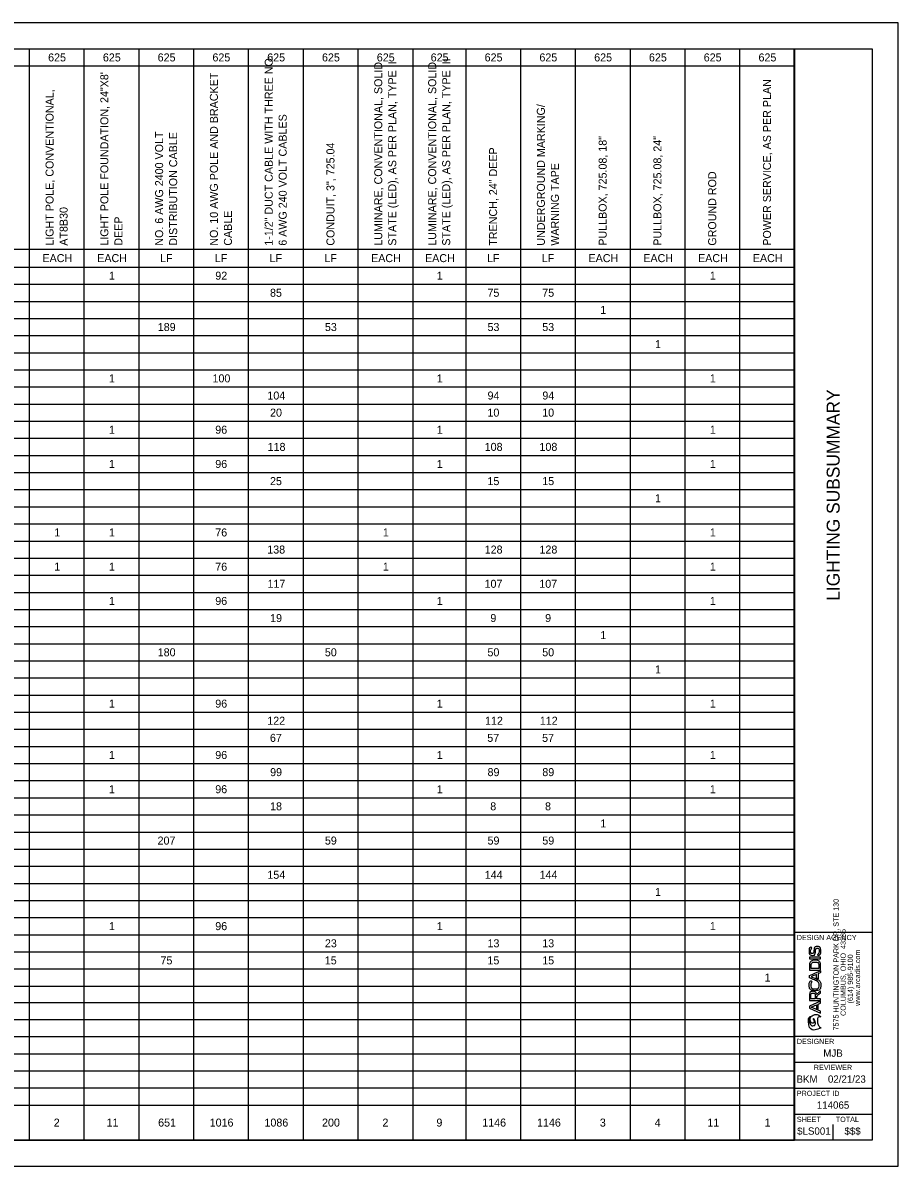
# Model space of a CAD drawing. Extents: x 0 to 34, y 0 to 22.
# Drawn here: x 17.16 to 34, y 0 to 22 of the extents above; entities that cross this region are included whole.
import ezdxf

# ---------------------------------------------------------------- set-up
doc = ezdxf.new("R2010")
doc.units = 0
for name, color, linetype in [('SH_Border', 7, 'Continuous'), ('SH_Cut_Line', 7, 'Continuous'), ('SH_Data', 7, 'Continuous'), ('SH_Text', 7, 'Continuous')]:
    doc.layers.add(name, color=color, linetype=linetype)

msp = doc.modelspace()

# ---------------------------------------------------------------- linework, layer by layer
at = {"layer": 'SH_Border'}
for p, q in [((32, 0.5), (32, 21.5)), ((32, 4.5), (33.5, 4.5)), ((32, 2.5), (33.5, 2.5)), ((32, 2), (33.5, 2)), ((32, 1.5), (33.5, 1.5)), ((32, 1), (33.5, 1))]:
    msp.add_line(p, q, dxfattribs=at)
msp.add_lwpolyline([(1.5, 21.5), (33.5, 21.5), (33.5, 0.5), (1.5, 0.5)], close=True, dxfattribs=at)
at = {"layer": 'SH_Cut_Line'}
msp.add_lwpolyline([(0, 0), (34, 0), (34, 22), (0, 22)], close=True, dxfattribs=at)
at = {"layer": 'SH_Data'}
for p, q in [((32.507, 4.022), (32.292, 4.022)), ((32.292, 4.022), (32.292, 3.988)), ((32.507, 4.022), (32.292, 4.022)), ((32.292, 4.022), (32.292, 3.988)), ((32.292, 3.988), (32.507, 3.988)), ((32.292, 3.988), (32.507, 3.988)), ((32.507, 3.988), (32.507, 4.022)), ((32.507, 3.988), (32.507, 4.022)), ((32.75, 3.5), (32.75, 3.5)), ((32.75, 3.5), (32.75, 3.5)), ((32.75, 3.5), (32.75, 3.5)), ((32.507, 3.175), (32.292, 3.079)), ((32.507, 3.175), (32.292, 3.079)), ((32.328, 3.06), (32.431, 3.105)), ((32.328, 3.06), (32.431, 3.105)), ((32.431, 3.105), (32.431, 3.034)), ((32.431, 3.105), (32.431, 3.034)), ((32.462, 3.119), (32.507, 3.139)), ((32.462, 3.119), (32.507, 3.139)), ((32.462, 3.02), (32.462, 3.119)), ((32.462, 3.02), (32.462, 3.119)), ((32.507, 3.139), (32.507, 3.175)), ((32.507, 3.139), (32.507, 3.175)), ((32.292, 3.079), (32.292, 3.041)), ((32.292, 3.079), (32.292, 3.041)), ((32.292, 3.041), (32.507, 2.945)), ((32.292, 3.041), (32.507, 2.945)), ((32.507, 2.981), (32.328, 3.06)), ((32.507, 2.981), (32.328, 3.06)), ((32.431, 3.034), (32.462, 3.02)), ((32.431, 3.034), (32.462, 3.02)), ((32.507, 2.945), (32.507, 2.981)), ((32.507, 2.945), (32.507, 2.981)), ((32.375, 0.675), (32.375, 0.675)), ((32.75, 0.5), (32.75, 0.8))]:
    msp.add_line(p, q, dxfattribs=at)
for points, degree in [([(32.34, 4.193), (32.325, 4.183), (32.316, 4.163), (32.316, 4.14), (32.316, 4.111), (32.328, 4.09), (32.348, 4.09), (32.369, 4.09), (32.375, 4.114), (32.379, 4.143), (32.385, 4.187), (32.398, 4.229), (32.446, 4.229), (32.494, 4.229), (32.512, 4.185), (32.512, 4.14), (32.512, 4.099), (32.5, 4.067), (32.463, 4.047), (32.463, 4.047), (32.446, 4.073), (32.446, 4.073), (32.472, 4.088), (32.482, 4.115), (32.482, 4.14), (32.482, 4.166), (32.473, 4.195), (32.446, 4.195), (32.422, 4.195), (32.414, 4.17), (32.41, 4.14), (32.405, 4.097), (32.394, 4.056), (32.348, 4.056), (32.303, 4.056), (32.286, 4.1), (32.286, 4.139), (32.286, 4.17), (32.293, 4.201), (32.322, 4.22), (32.322, 4.22), (32.34, 4.193), (32.34, 4.193), (32.34, 4.193), (32.34, 4.193), (32.34, 4.193)], 3), ([(32.34, 4.193), (32.325, 4.183), (32.316, 4.163), (32.316, 4.14), (32.316, 4.111), (32.328, 4.09), (32.348, 4.09), (32.369, 4.09), (32.375, 4.114), (32.379, 4.143), (32.385, 4.187), (32.398, 4.229), (32.446, 4.229), (32.494, 4.229), (32.512, 4.185), (32.512, 4.14), (32.512, 4.099), (32.5, 4.067), (32.463, 4.047), (32.463, 4.047), (32.446, 4.073), (32.446, 4.073), (32.472, 4.088), (32.482, 4.115), (32.482, 4.14), (32.482, 4.166), (32.473, 4.195), (32.446, 4.195), (32.422, 4.195), (32.414, 4.17), (32.41, 4.14), (32.405, 4.097), (32.394, 4.056), (32.348, 4.056), (32.303, 4.056), (32.286, 4.1), (32.286, 4.139), (32.286, 4.17), (32.293, 4.201), (32.322, 4.22), (32.322, 4.22), (32.34, 4.193), (32.34, 4.193), (32.34, 4.193), (32.34, 4.193), (32.34, 4.193)], 3), ([(32.292, 3.772), (32.292, 3.772), (32.507, 3.772), (32.507, 3.772), (32.507, 3.772), (32.507, 3.854), (32.507, 3.854), (32.507, 3.929), (32.452, 3.963), (32.398, 3.962), (32.345, 3.961), (32.292, 3.927), (32.292, 3.854)], 3), ([(32.292, 3.772), (32.292, 3.772), (32.507, 3.772), (32.507, 3.772), (32.507, 3.772), (32.507, 3.854), (32.507, 3.854), (32.507, 3.929), (32.452, 3.963), (32.398, 3.962), (32.345, 3.961), (32.292, 3.927), (32.292, 3.854)], 3), ([(32.292, 3.664), (32.292, 3.664), (32.292, 3.626), (32.292, 3.626), (32.292, 3.626), (32.432, 3.563), (32.432, 3.563), (32.432, 3.563), (32.432, 3.563), (32.432, 3.563), (32.445, 3.557), (32.453, 3.549), (32.456, 3.547), (32.471, 3.532), (32.479, 3.51), (32.479, 3.49), (32.479, 3.434), (32.44, 3.411), (32.401, 3.41), (32.361, 3.41), (32.321, 3.435), (32.321, 3.49), (32.321, 3.51), (32.328, 3.53), (32.343, 3.545), (32.343, 3.545), (32.321, 3.569), (32.321, 3.569), (32.299, 3.547), (32.288, 3.519), (32.288, 3.49), (32.288, 3.413), (32.345, 3.376), (32.401, 3.376), (32.458, 3.376), (32.512, 3.412), (32.512, 3.49), (32.512, 3.52), (32.502, 3.549), (32.48, 3.571), (32.48, 3.571), (32.466, 3.584), (32.446, 3.593), (32.446, 3.593), (32.44, 3.596), (32.44, 3.596), (32.44, 3.596), (32.425, 3.602), (32.425, 3.602), (32.425, 3.602), (32.425, 3.602), (32.425, 3.602), (32.425, 3.602), (32.328, 3.645), (32.328, 3.645), (32.328, 3.645), (32.431, 3.69), (32.431, 3.69), (32.431, 3.69), (32.431, 3.619), (32.431, 3.619), (32.431, 3.619), (32.462, 3.605), (32.462, 3.605), (32.462, 3.605), (32.462, 3.704), (32.462, 3.704), (32.462, 3.704), (32.507, 3.724), (32.507, 3.724), (32.507, 3.724), (32.507, 3.76), (32.507, 3.76), (32.507, 3.76), (32.292, 3.664), (32.292, 3.664), (32.292, 3.664), (32.292, 3.664), (32.292, 3.664)], 3), ([(32.292, 3.664), (32.292, 3.664), (32.292, 3.626), (32.292, 3.626), (32.292, 3.626), (32.432, 3.563), (32.432, 3.563), (32.432, 3.563), (32.432, 3.563), (32.432, 3.563), (32.445, 3.557), (32.453, 3.549), (32.456, 3.547), (32.471, 3.532), (32.479, 3.51), (32.479, 3.49), (32.479, 3.434), (32.44, 3.411), (32.401, 3.41), (32.361, 3.41), (32.321, 3.435), (32.321, 3.49), (32.321, 3.51), (32.328, 3.53), (32.343, 3.545), (32.343, 3.545), (32.321, 3.569), (32.321, 3.569), (32.299, 3.547), (32.288, 3.519), (32.288, 3.49), (32.288, 3.413), (32.345, 3.376), (32.401, 3.376), (32.458, 3.376), (32.512, 3.412), (32.512, 3.49), (32.512, 3.52), (32.502, 3.549), (32.48, 3.571), (32.48, 3.571), (32.466, 3.584), (32.446, 3.593), (32.446, 3.593), (32.44, 3.596), (32.44, 3.596), (32.44, 3.596), (32.425, 3.602), (32.425, 3.602), (32.425, 3.602), (32.425, 3.602), (32.425, 3.602), (32.425, 3.602), (32.328, 3.645), (32.328, 3.645), (32.328, 3.645), (32.431, 3.69), (32.431, 3.69), (32.431, 3.69), (32.431, 3.619), (32.431, 3.619), (32.431, 3.619), (32.462, 3.605), (32.462, 3.605), (32.462, 3.605), (32.462, 3.704), (32.462, 3.704), (32.462, 3.704), (32.507, 3.724), (32.507, 3.724), (32.507, 3.724), (32.507, 3.76), (32.507, 3.76), (32.507, 3.76), (32.292, 3.664), (32.292, 3.664), (32.292, 3.664), (32.292, 3.664), (32.292, 3.664)], 3), ([(32.292, 3.854), (32.292, 3.854), (32.292, 3.772), (32.292, 3.772)], 2), ([(32.292, 3.854), (32.292, 3.854), (32.292, 3.772), (32.292, 3.772)], 2), ([(32.474, 3.806), (32.474, 3.806), (32.325, 3.806), (32.325, 3.806)], 2), ([(32.474, 3.806), (32.474, 3.806), (32.325, 3.806), (32.325, 3.806)], 2), ([(32.325, 3.806), (32.325, 3.806), (32.325, 3.854), (32.325, 3.854), (32.325, 3.905), (32.361, 3.927), (32.398, 3.928), (32.435, 3.929), (32.474, 3.906), (32.474, 3.854), (32.474, 3.854), (32.474, 3.806), (32.474, 3.806)], 3), ([(32.325, 3.806), (32.325, 3.806), (32.325, 3.854), (32.325, 3.854), (32.325, 3.905), (32.361, 3.927), (32.398, 3.928), (32.435, 3.929), (32.474, 3.906), (32.474, 3.854), (32.474, 3.854), (32.474, 3.806), (32.474, 3.806)], 3), ([(32.43, 3.305), (32.423, 3.348), (32.393, 3.364), (32.362, 3.364), (32.326, 3.364), (32.292, 3.337), (32.292, 3.288), (32.292, 3.254), (32.292, 3.221), (32.292, 3.187), (32.292, 3.187), (32.507, 3.187), (32.507, 3.187), (32.507, 3.187), (32.507, 3.222), (32.507, 3.222), (32.507, 3.222), (32.433, 3.222), (32.433, 3.222), (32.433, 3.222), (32.433, 3.267), (32.433, 3.267), (32.433, 3.267), (32.507, 3.333), (32.507, 3.333), (32.507, 3.333), (32.507, 3.373), (32.507, 3.373)], 3), ([(32.43, 3.305), (32.423, 3.348), (32.393, 3.364), (32.362, 3.364), (32.326, 3.364), (32.292, 3.337), (32.292, 3.288), (32.292, 3.254), (32.292, 3.221), (32.292, 3.187), (32.292, 3.187), (32.507, 3.187), (32.507, 3.187), (32.507, 3.187), (32.507, 3.222), (32.507, 3.222), (32.507, 3.222), (32.433, 3.222), (32.433, 3.222), (32.433, 3.222), (32.433, 3.267), (32.433, 3.267), (32.433, 3.267), (32.507, 3.333), (32.507, 3.333), (32.507, 3.333), (32.507, 3.373), (32.507, 3.373)], 3), ([(32.323, 3.288), (32.323, 3.316), (32.344, 3.329), (32.363, 3.329), (32.383, 3.329), (32.402, 3.316), (32.402, 3.287), (32.402, 3.287), (32.402, 3.222), (32.402, 3.222), (32.402, 3.222), (32.323, 3.222), (32.323, 3.222)], 3), ([(32.323, 3.288), (32.323, 3.316), (32.344, 3.329), (32.363, 3.329), (32.383, 3.329), (32.402, 3.316), (32.402, 3.287), (32.402, 3.287), (32.402, 3.222), (32.402, 3.222), (32.402, 3.222), (32.323, 3.222), (32.323, 3.222)], 3), ([(32.507, 3.373), (32.507, 3.373), (32.43, 3.305), (32.43, 3.305)], 2), ([(32.507, 3.373), (32.507, 3.373), (32.43, 3.305), (32.43, 3.305)], 2), ([(32.323, 3.222), (32.323, 3.222), (32.323, 3.288), (32.323, 3.288)], 2), ([(32.323, 3.222), (32.323, 3.222), (32.323, 3.288), (32.323, 3.288)], 2), ([(32.272, 2.786), (32.282, 2.575), (32.514, 2.656), (32.514, 2.656), (32.494, 2.674), (32.446, 2.734), (32.446, 2.817), (32.446, 2.817), (32.446, 2.817), (32.446, 2.818), (32.446, 2.858), (32.48, 2.881), (32.514, 2.872), (32.514, 2.872), (32.441, 2.935), (32.357, 2.9), (32.329, 2.888), (32.309, 2.857), (32.309, 2.821), (32.309, 2.808), (32.311, 2.795), (32.316, 2.782), (32.329, 2.752), (32.356, 2.748), (32.369, 2.754), (32.378, 2.759), (32.383, 2.768), (32.383, 2.777), (32.383, 2.779), (32.383, 2.781), (32.383, 2.782), (32.378, 2.813), (32.364, 2.826), (32.364, 2.833), (32.364, 2.834), (32.364, 2.835), (32.365, 2.835), (32.368, 2.84), (32.383, 2.836), (32.398, 2.796), (32.402, 2.787), (32.407, 2.769), (32.407, 2.752), (32.407, 2.732), (32.401, 2.712), (32.38, 2.706), (32.343, 2.693), (32.298, 2.738), (32.293, 2.804), (32.292, 2.807), (32.292, 2.812), (32.292, 2.815), (32.292, 2.849), (32.307, 2.873), (32.317, 2.885), (32.294, 2.871), (32.273, 2.842), (32.272, 2.796), (32.272, 2.796), (32.272, 2.792), (32.272, 2.786), (32.272, 2.786), (32.272, 2.786), (32.272, 2.786)], 3), ([(32.272, 2.786), (32.282, 2.575), (32.514, 2.656), (32.514, 2.656), (32.494, 2.674), (32.446, 2.734), (32.446, 2.817), (32.446, 2.817), (32.446, 2.817), (32.446, 2.818), (32.446, 2.858), (32.48, 2.881), (32.514, 2.872), (32.514, 2.872), (32.441, 2.935), (32.357, 2.9), (32.329, 2.888), (32.309, 2.857), (32.309, 2.821), (32.309, 2.808), (32.311, 2.795), (32.316, 2.782), (32.329, 2.752), (32.356, 2.748), (32.369, 2.754), (32.378, 2.759), (32.383, 2.768), (32.383, 2.777), (32.383, 2.779), (32.383, 2.781), (32.383, 2.782), (32.378, 2.813), (32.364, 2.826), (32.364, 2.833), (32.364, 2.834), (32.364, 2.835), (32.365, 2.835), (32.368, 2.84), (32.383, 2.836), (32.398, 2.796), (32.402, 2.787), (32.407, 2.769), (32.407, 2.752), (32.407, 2.732), (32.401, 2.712), (32.38, 2.706), (32.343, 2.693), (32.298, 2.738), (32.293, 2.804), (32.292, 2.807), (32.292, 2.812), (32.292, 2.815), (32.292, 2.849), (32.307, 2.873), (32.317, 2.885), (32.294, 2.871), (32.273, 2.842), (32.272, 2.796), (32.272, 2.796), (32.272, 2.792), (32.272, 2.786), (32.272, 2.786), (32.272, 2.786), (32.272, 2.786)], 3)]:
    msp.add_open_spline(points, degree=degree, dxfattribs=at)
at = {"layer": 'SH_Text'}
for p, q in [((1.5, 21.5), (32.004, 21.5)), ((17.279, 21.5), (17.279, 0.5)), ((18.333, 21.5), (18.333, 0.5)), ((19.387, 21.5), (19.387, 0.5)), ((20.441, 21.5), (20.441, 0.5)), ((21.495, 21.5), (21.495, 0.5)), ((22.549, 21.5), (22.549, 0.5)), ((23.604, 21.5), (23.604, 0.5)), ((24.658, 21.5), (24.658, 0.5)), ((25.679, 21.5), (25.679, 0.5)), ((26.733, 21.5), (26.733, 0.5)), ((27.787, 21.5), (27.787, 0.5)), ((28.841, 21.5), (28.841, 0.5)), ((29.895, 21.5), (29.895, 0.5)), ((30.949, 21.5), (30.949, 0.5)), ((32.004, 21.5), (32.004, 0.5)), ((10.954, 21.171), (32.004, 21.171)), ((10.954, 17.646), (32.004, 17.646)), ((1.5, 17.3), (32.004, 17.3)), ((1.5, 16.971), (32.004, 16.971)), ((1.5, 16.641), (32.004, 16.641)), ((1.5, 16.312), (32.004, 16.312)), ((1.5, 15.982), (32.004, 15.982)), ((1.5, 15.653), (32.004, 15.653)), ((1.5, 15.324), (32.004, 15.324)), ((1.5, 14.994), (32.004, 14.994)), ((1.5, 14.665), (32.004, 14.665)), ((1.5, 14.335), (32.004, 14.335)), ((1.5, 14.006), (32.004, 14.006)), ((1.5, 13.676), (32.004, 13.676)), ((1.5, 13.347), (32.004, 13.347)), ((1.5, 13.018), (32.004, 13.018)), ((1.5, 12.688), (32.004, 12.688)), ((1.5, 12.359), (32.004, 12.359)), ((1.5, 12.029), (32.004, 12.029)), ((1.5, 11.7), (32.004, 11.7)), ((1.5, 11.371), (32.004, 11.371)), ((1.5, 11.041), (32.004, 11.041)), ((1.5, 10.712), (32.004, 10.712)), ((1.5, 10.382), (32.004, 10.382)), ((1.5, 10.053), (32.004, 10.053)), ((1.5, 9.724), (32.004, 9.724)), ((1.5, 9.394), (32.004, 9.394)), ((1.5, 9.065), (32.004, 9.065)), ((1.5, 8.735), (32.004, 8.735)), ((1.5, 8.406), (32.004, 8.406)), ((1.5, 8.076), (32.004, 8.076)), ((1.5, 7.747), (32.004, 7.747)), ((1.5, 7.418), (32.004, 7.418)), ((1.5, 7.088), (32.004, 7.088)), ((1.5, 6.759), (32.004, 6.759)), ((1.5, 6.429), (32.004, 6.429)), ((1.5, 6.1), (32.004, 6.1)), ((1.5, 5.771), (32.004, 5.771)), ((1.5, 5.441), (32.004, 5.441)), ((1.5, 5.112), (32.004, 5.112)), ((1.5, 4.782), (32.004, 4.782)), ((1.5, 4.453), (32.004, 4.453)), ((1.5, 4.124), (32.004, 4.124)), ((1.5, 3.794), (32.004, 3.794)), ((1.5, 3.465), (32.004, 3.465)), ((1.5, 3.152), (32.004, 3.152)), ((1.5, 2.822), (32.004, 2.822)), ((1.5, 2.493), (32.004, 2.493)), ((1.5, 2.164), (32.004, 2.164)), ((1.5, 1.834), (32.004, 1.834)), ((1.5, 1.505), (32.004, 1.505)), ((1.5, 1.175), (32.004, 1.175)), ((1.5, 0.5), (32.004, 0.5))]:
    msp.add_line(p, q, dxfattribs=at)

# ---------------------------------------------------------------- texts
at = {"layer": 'SH_Data'}
for s, height, p in [('LIGHTING SUBSUMMARY', 0.25, (32.875, 10.879)), ('7575 HUNTINGTON PARK DR, STE 130', 0.1, (32.855, 2.611)), ('7575 HUNTINGTON PARK DR, STE 130', 0.1, (32.855, 2.611)), ('COLUMBUS, OHIO  43235', 0.1, (32.992, 2.89)), ('COLUMBUS, OHIO  43235', 0.1, (32.992, 2.89)), ('(614) 985-9100', 0.1, (33.13, 3.13)), ('(614) 985-9100', 0.1, (33.13, 3.13)), ('www.arcadis.com', 0.1, (33.268, 3.085)), ('www.arcadis.com', 0.1, (33.268, 3.085))]:
    msp.add_text(s, height=height, rotation=90, dxfattribs=at).set_placement(p)
for s, height, p in [('DESIGN AGENCY', 0.1, (32.05, 4.35)), ('DESIGNER', 0.1, (32.05, 2.35)), ('MJB', 0.14, (32.56, 2.105)), ('REVIEWER', 0.1, (32.378, 1.85)), ('BKM', 0.14, (32.045, 1.605)), ('02/21/23', 0.14, (32.649, 1.605)), ('PROJECT ID', 0.1, (32.05, 1.35)), ('114065', 0.14, (32.435, 1.105)), ('SHEET', 0.1, (32.05, 0.85)), ('TOTAL', 0.1, (32.8, 0.85)), ('$LS001', 0.14, (32.056, 0.605)), ('$$$', 0.14, (32.967, 0.605))]:
    msp.add_text(s, height=height, dxfattribs=at).set_placement(p)
at = {"layer": 'SH_Text'}
for s, p in [('625', (17.643, 21.258)), ('625', (18.697, 21.258)), ('625', (19.751, 21.258)), ('625', (20.805, 21.258)), ('625', (21.859, 21.258)), ('625', (22.913, 21.258)), ('625', (23.968, 21.258)), ('625', (25.005, 21.258)), ('625', (26.043, 21.258)), ('625', (27.097, 21.258)), ('625', (28.151, 21.258)), ('625', (29.205, 21.258)), ('625', (30.259, 21.258)), ('625', (31.313, 21.258)), ('EACH', (17.534, 17.396)), ('EACH', (18.588, 17.396)), ('LF', (19.796, 17.396)), ('LF', (20.851, 17.396)), ('LF', (21.905, 17.396)), ('LF', (22.959, 17.396)), ('EACH', (23.858, 17.396)), ('EACH', (24.896, 17.396)), ('LF', (26.088, 17.396)), ('LF', (27.142, 17.396)), ('EACH', (28.042, 17.396)), ('EACH', (29.096, 17.396)), ('EACH', (30.15, 17.396)), ('EACH', (31.204, 17.396)), ('1', (18.814, 17.058)), ('92', (20.86, 17.058)), ('1', (25.122, 17.058)), ('1', (30.376, 17.058)), ('85', (21.913, 16.729)), ('75', (26.097, 16.729)), ('75', (27.151, 16.729)), ('1', (28.268, 16.399)), ('189', (19.753, 16.07)), ('53', (22.969, 16.07)), ('53', (26.098, 16.07)), ('53', (27.152, 16.07)), ('1', (29.322, 15.741)), ('1', (18.814, 15.082)), ('100', (20.806, 15.082)), ('1', (25.122, 15.082)), ('1', (30.376, 15.082)), ('104', (21.862, 14.752)), ('94', (26.099, 14.752)), ('94', (27.154, 14.752)), ('20', (21.914, 14.423)), ('10', (26.097, 14.423)), ('10', (27.151, 14.423)), ('1', (18.814, 14.094)), ('96', (20.859, 14.094)), ('1', (25.122, 14.094)), ('1', (30.376, 14.094)), ('118', (21.867, 13.764)), ('108', (26.044, 13.764)), ('108', (27.098, 13.764)), ('1', (18.814, 13.435)), ('96', (20.859, 13.435)), ('1', (25.122, 13.435)), ('1', (30.376, 13.435)), ('25', (21.913, 13.105)), ('15', (26.097, 13.105)), ('15', (27.151, 13.105)), ('1', (29.322, 12.776)), ('1', (17.76, 12.117)), ('1', (18.814, 12.117)), ('76', (20.859, 12.117)), ('1', (24.084, 12.117)), ('1', (30.376, 12.117)), ('138', (21.86, 11.788)), ('128', (26.044, 11.788)), ('128', (27.098, 11.788)), ('1', (17.76, 11.458)), ('1', (18.814, 11.458)), ('76', (20.859, 11.458)), ('1', (24.084, 11.458)), ('1', (30.376, 11.458)), ('117', (21.864, 11.129)), ('107', (26.041, 11.129)), ('107', (27.095, 11.129)), ('1', (18.814, 10.799)), ('96', (20.859, 10.799)), ('1', (25.122, 10.799)), ('1', (30.376, 10.799)), ('19', (21.915, 10.47)), ('9', (26.153, 10.47)), ('9', (27.207, 10.47)), ('1', (28.268, 10.141)), ('180', (19.752, 9.811)), ('50', (22.968, 9.811)), ('50', (26.097, 9.811)), ('50', (27.151, 9.811)), ('1', (29.322, 9.482)), ('1', (18.814, 8.823)), ('96', (20.859, 8.823)), ('1', (25.122, 8.823)), ('1', (30.376, 8.823)), ('122', (21.86, 8.494)), ('112', (26.051, 8.494)), ('112', (27.105, 8.494)), ('67', (21.911, 8.164)), ('57', (26.094, 8.164)), ('57', (27.149, 8.164)), ('1', (18.814, 7.835)), ('96', (20.859, 7.835)), ('1', (25.122, 7.835)), ('1', (30.376, 7.835)), ('99', (21.915, 7.505)), ('89', (26.099, 7.505)), ('89', (27.153, 7.505)), ('1', (18.814, 7.176)), ('96', (20.859, 7.176)), ('1', (25.122, 7.176)), ('1', (30.376, 7.176)), ('18', (21.914, 6.847)), ('8', (26.151, 6.847)), ('8', (27.205, 6.847)), ('1', (28.268, 6.517)), ('207', (19.749, 6.188)), ('59', (22.969, 6.188)), ('59', (26.099, 6.188)), ('59', (27.153, 6.188)), ('154', (21.862, 5.529)), ('144', (26.046, 5.529)), ('144', (27.1, 5.529)), ('1', (29.322, 5.199)), ('1', (18.814, 4.541)), ('96', (20.859, 4.541)), ('1', (25.122, 4.541)), ('1', (30.376, 4.541)), ('23', (22.969, 4.211)), ('13', (26.098, 4.211)), ('13', (27.152, 4.211)), ('75', (19.805, 3.882)), ('15', (22.967, 3.882)), ('15', (26.097, 3.882)), ('15', (27.151, 3.882)), ('1', (31.43, 3.552)), ('2', (17.751, 0.761)), ('11', (18.767, 0.761)), ('651', (19.76, 0.761)), ('1016', (20.752, 0.761)), ('1086', (21.806, 0.761)), ('200', (22.914, 0.761)), ('2', (24.076, 0.761)), ('9', (25.115, 0.761)), ('1146', (25.997, 0.761)), ('1146', (27.051, 0.761)), ('3', (28.26, 0.761)), ('4', (29.316, 0.761)), ('11', (30.329, 0.761)), ('1', (31.43, 0.761))]:
    msp.add_text(s, height=0.154, dxfattribs=at).set_placement(p)
for s, p in [('1-1/2" DUCT CABLE WITH THREE NO. ', (21.965, 17.712)), ('LUMINARE, CONVENTIONAL, SOLID ', (24.073, 17.712)), ('STATE (LED), AS PER PLAN, TYPE II', (24.342, 17.712)), ('LUMINARE, CONVENTIONAL, SOLID ', (25.111, 17.712)), ('STATE (LED), AS PER PLAN, TYPE III', (25.38, 17.712)), ('LIGHT POLE FOUNDATION, 24"X8\' ', (18.802, 17.712)), ('NO. 10 AWG POLE AND BRACKET ', (20.91, 17.712)), ('LIGHT POLE, CONVENTIONAL, ', (17.748, 17.712)), ('POWER SERVICE, AS PER PLAN', (31.553, 17.712)), ('UNDERGROUND MARKING/ ', (27.202, 17.712)), ('6 AWG 240 VOLT CABLES', (22.234, 17.712)), ('NO. 6 AWG 2400 VOLT ', (19.856, 17.712)), ('DISTRIBUTION CABLE', (20.126, 17.712)), ('PULLBOX, 725.08, 18"', (28.391, 17.712)), ('PULLBOX, 725.08, 24"', (29.445, 17.712)), ('CONDUIT, 3", 725.04', (23.153, 17.712)), ('TRENCH, 24" DEEP', (26.283, 17.712)), ('WARNING TAPE', (27.472, 17.712)), ('GROUND ROD', (30.499, 17.712)), ('AT8B30', (18.018, 17.712)), ('DEEP', (19.072, 17.712)), ('CABLE', (21.18, 17.712))]:
    msp.add_text(s, height=0.154, rotation=90, dxfattribs=at).set_placement(p)

doc.saveas('drawing.dxf')
